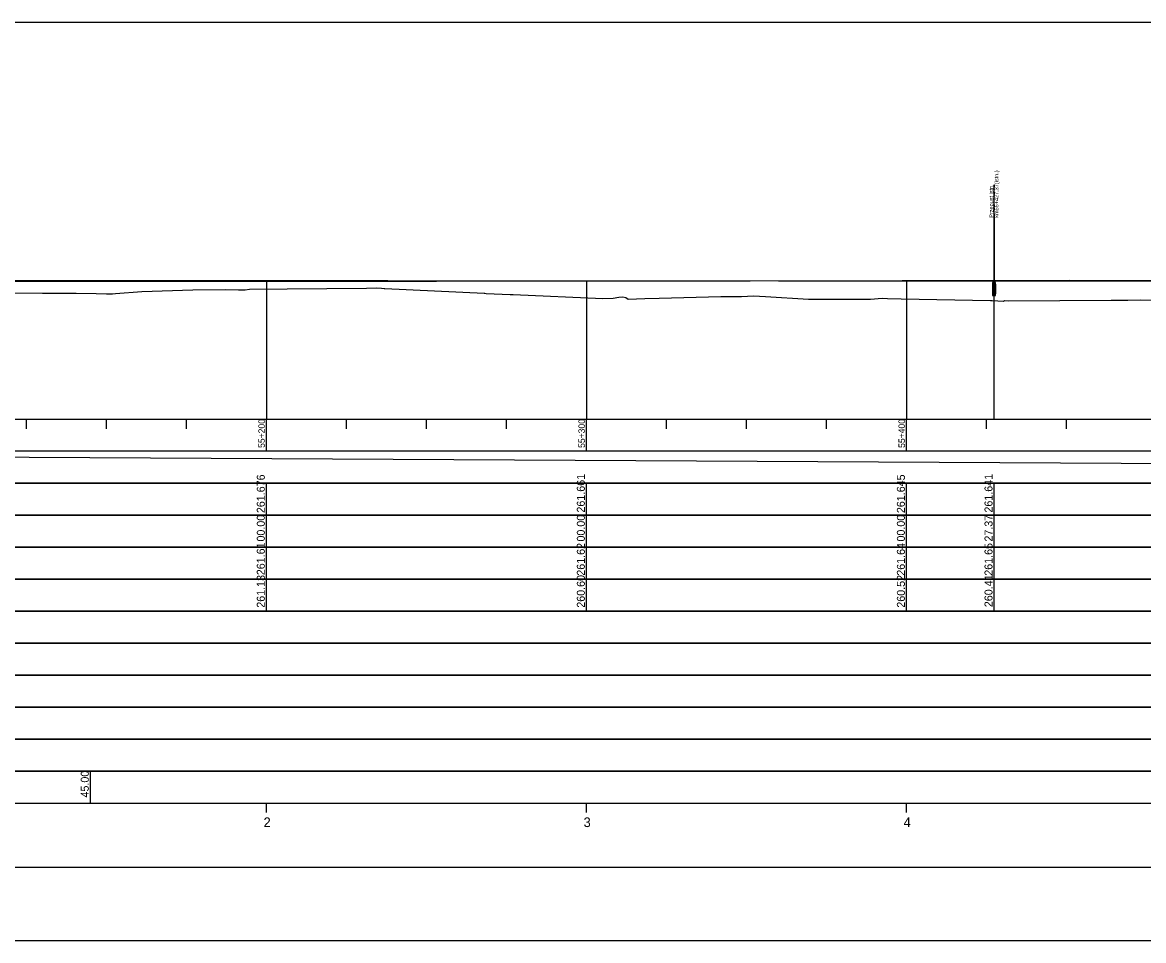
# Model space of a CAD drawing. Extents: x 6445630 to 6518227, y 5499240 to 5511716.
# Drawn here: x 6454355 to 6454705.3, y 5508966.7 to 5509253.7 of the extents above; entities that cross this region are included whole.
import ezdxf

# ---------------------------------------------------------------- set-up
doc = ezdxf.new("R2010")
doc.units = 0
for name, color, linetype in [('Default', 7, 'Continuous'), ('TOR_PROF-obiekty+opisy', 7, 'Continuous'), ('TOR_PROF-tabelka-geometria T1', 7, 'Continuous'), ('TOR_PROF-tabelka-kilometracja', 7, 'Continuous'), ('TOR_PROF-tabelka-odleglosci T1', 7, 'Continuous'), ('TOR_PROF-tabelka-pochylenia proj T1', 7, 'Continuous'), ('TOR_PROF-tabelka-rodzaj rowu T1', 7, 'Continuous'), ('TOR_PROF-tabelka-rowyT1', 7, 'Continuous'), ('TOR_PROF-tabelka-rurociagi T1', 7, 'Continuous'), ('TOR_PROF-tabelka-rzedne istn T1', 7, 'Continuous'), ('TOR_PROF-tabelka-rzedne proj T1', 7, 'Continuous'), ('TOR_PROF-tabelka-teren istniejacy T1', 7, 'Continuous'), ('TOR_PROF-tabelka-warstwa ochronna T1', 7, 'Continuous'), ('TOR_PROF-tor istniejacy T1', 7, 'Continuous'), ('TOR_PROF-tor projektowany', 7, 'Continuous'), ('TOR_PROF-uklad odniesienia', 7, 'Continuous'), ('TOR_PROF-warstwa ochronna', 7, 'Continuous'), ('TOR_RAMKI-dodatkowe3', 7, 'Continuous'), ('TOR_RAMKI-MASKA WYCIECIA', 7, 'Continuous')]:
    doc.layers.add(name, color=color, linetype=linetype)

msp = doc.modelspace()

# ---------------------------------------------------------------- linework, layer by layer
at = {"layer": 'TOR_PROF-obiekty+opisy'}
for p, q in [((6454658.59, 5509129.74), (6454658.59, 5509202.94)), ((6454658.59, 5509193.94), (6454658.59, 5509172.94)), ((6454658.59, 5509193.94), (6454658.59, 5509172.94))]:
    msp.add_line(p, q, dxfattribs=at)
for points in [[(6454659.05, 5509172.45), (6454658.13, 5509172.45), (6454658.13, 5509168.37), (6454659.05, 5509168.37)], [(6454658.97, 5509171.91), (6454658.22, 5509171.91), (6454658.22, 5509168.91), (6454658.97, 5509168.91)]]:
    msp.add_lwpolyline(points, close=True, dxfattribs=at)
for points in [[(6454659.05, 5509168.37), (6454659.05, 5509172.45), (6454658.13, 5509172.45), (6454658.13, 5509168.37), (6454659.05, 5509168.37)], [(6454658.97, 5509168.91), (6454658.22, 5509168.91), (6454658.22, 5509171.91), (6454658.97, 5509171.91), (6454658.97, 5509168.91)]]:
    msp.add_lwpolyline(points, dxfattribs=at)
at = {"layer": 'TOR_PROF-tabelka-geometria T1'}
for points in [[(6452331.21, 5508989.74), (6462728.4, 5508989.74)], [(6452331.21, 5508989.74), (6462731.21, 5508989.74)]]:
    msp.add_lwpolyline(points, dxfattribs=at)
at = {"layer": 'TOR_PROF-tabelka-kilometracja'}
for points in [[(6454431.21, 5509006.74), (6454431.21, 5509009.74)], [(6454531.21, 5509006.74), (6454531.21, 5509009.74)], [(6454631.21, 5509006.74), (6454631.21, 5509009.74)]]:
    msp.add_lwpolyline(points, dxfattribs=at)
at = {"layer": 'TOR_PROF-tabelka-odleglosci T1'}
msp.add_lwpolyline([(6452331.21, 5509089.74), (6462731.21, 5509089.74), (6462731.21, 5509099.74), (6452331.21, 5509099.74)], close=True, dxfattribs=at)
for points in [[(6454431.21, 5509089.74), (6454431.21, 5509099.74)], [(6454531.21, 5509089.74), (6454531.21, 5509099.74)], [(6454631.21, 5509089.74), (6454631.21, 5509099.74)], [(6454658.59, 5509089.74), (6454658.59, 5509099.74)]]:
    msp.add_lwpolyline(points, dxfattribs=at)
at = {"layer": 'TOR_PROF-tabelka-pochylenia proj T1'}
msp.add_lwpolyline([(6452331.21, 5509109.74), (6462731.21, 5509109.74), (6462731.21, 5509119.74), (6452331.21, 5509119.74)], close=True, dxfattribs=at)
msp.add_lwpolyline([(6454281.21, 5509118.24), (6455551.21, 5509111.24)], dxfattribs=at)
at = {"layer": 'TOR_PROF-tabelka-rodzaj rowu T1'}
for points in [[(6452331.21, 5509049.74), (6462731.21, 5509049.74), (6462731.21, 5509059.74), (6452331.21, 5509059.74)], [(6452331.21, 5509029.74), (6462731.21, 5509029.74), (6462731.21, 5509039.74), (6452331.21, 5509039.74)]]:
    msp.add_lwpolyline(points, close=True, dxfattribs=at)
at = {"layer": 'TOR_PROF-tabelka-rowyT1'}
msp.add_lwpolyline([(6452331.21, 5509059.74), (6462731.21, 5509059.74), (6462731.21, 5509069.74), (6452331.21, 5509069.74)], close=True, dxfattribs=at)
at = {"layer": 'TOR_PROF-tabelka-rurociagi T1'}
msp.add_lwpolyline([(6452331.21, 5509039.74), (6462731.21, 5509039.74), (6462731.21, 5509049.74), (6452331.21, 5509049.74)], close=True, dxfattribs=at)
at = {"layer": 'TOR_PROF-tabelka-rzedne istn T1'}
msp.add_lwpolyline([(6452331.21, 5509079.74), (6462731.21, 5509079.74), (6462731.21, 5509089.74), (6452331.21, 5509089.74)], close=True, dxfattribs=at)
for points in [[(6454431.21, 5509079.74), (6454431.21, 5509089.74)], [(6454531.21, 5509079.74), (6454531.21, 5509089.74)], [(6454631.21, 5509079.74), (6454631.21, 5509089.74)], [(6454658.59, 5509079.74), (6454658.59, 5509089.74)], [(6454431.21, 5509069.74), (6454431.21, 5509079.74)], [(6454431.21, 5509069.74), (6454431.21, 5509079.74)], [(6454431.21, 5509069.74), (6454431.21, 5509079.74)], [(6454431.21, 5509069.74), (6454431.21, 5509079.74)], [(6454431.21, 5509069.74), (6454431.21, 5509079.74)], [(6454531.21, 5509069.74), (6454531.21, 5509079.74)], [(6454531.21, 5509069.74), (6454531.21, 5509079.74)], [(6454531.21, 5509069.74), (6454531.21, 5509079.74)], [(6454531.21, 5509069.74), (6454531.21, 5509079.74)], [(6454531.21, 5509069.74), (6454531.21, 5509079.74)], [(6454631.21, 5509069.74), (6454631.21, 5509079.74)], [(6454631.21, 5509069.74), (6454631.21, 5509079.74)], [(6454631.21, 5509069.74), (6454631.21, 5509079.74)], [(6454631.21, 5509069.74), (6454631.21, 5509079.74)], [(6454631.21, 5509069.74), (6454631.21, 5509079.74)], [(6454658.59, 5509069.74), (6454658.59, 5509079.74)]]:
    msp.add_lwpolyline(points, dxfattribs=at)
at = {"layer": 'TOR_PROF-tabelka-rzedne proj T1'}
msp.add_lwpolyline([(6452331.21, 5509099.74), (6462731.21, 5509099.74), (6462731.21, 5509109.74), (6452331.21, 5509109.74)], close=True, dxfattribs=at)
for points in [[(6454431.21, 5509099.74), (6454431.21, 5509109.74)], [(6454531.21, 5509099.74), (6454531.21, 5509109.74)], [(6454631.21, 5509099.74), (6454631.21, 5509109.74)], [(6454658.59, 5509099.74), (6454658.59, 5509109.74)]]:
    msp.add_lwpolyline(points, dxfattribs=at)
at = {"layer": 'TOR_PROF-tabelka-teren istniejacy T1'}
msp.add_lwpolyline([(6452331.21, 5509069.74), (6462731.21, 5509069.74), (6462731.21, 5509079.74), (6452331.21, 5509079.74)], close=True, dxfattribs=at)
msp.add_lwpolyline([(6452331.21, 5509069.74), (6462731.21, 5509069.74), (6462731.21, 5509079.74), (6452331.21, 5509079.74)], close=True, dxfattribs=at)
msp.add_lwpolyline([(6452331.21, 5509069.74), (6462731.21, 5509069.74), (6462731.21, 5509079.74), (6452331.21, 5509079.74)], close=True, dxfattribs=at)
msp.add_lwpolyline([(6452331.21, 5509069.74), (6462731.21, 5509069.74), (6462731.21, 5509079.74), (6452331.21, 5509079.74)], close=True, dxfattribs=at)
msp.add_lwpolyline([(6452331.21, 5509069.74), (6462731.21, 5509069.74), (6462731.21, 5509079.74), (6452331.21, 5509079.74)], close=True, dxfattribs=at)
at = {"layer": 'TOR_PROF-tabelka-warstwa ochronna T1'}
msp.add_lwpolyline([(6452331.21, 5509019.74), (6462731.21, 5509019.74), (6462731.21, 5509029.74), (6452331.21, 5509029.74)], close=True, dxfattribs=at)
at = {"layer": 'TOR_PROF-tor istniejacy T1'}
msp.add_lwpolyline([(6455080.92, 5509173.34), (6455031.47, 5509173.29), (6454982.25, 5509173.29), (6454932.13, 5509173.19), (6454881.27, 5509173.14), (6454830.82, 5509173.04), (6454782.24, 5509173.04), (6454734.36, 5509172.99), (6454682.23, 5509173.04), (6454629.84, 5509172.94), (6454582.4, 5509172.89), (6454537.18, 5509172.84), (6454484.35, 5509172.79), (6454432.02, 5509172.79), (6454381.42, 5509172.74), (6454331.32, 5509172.69)], dxfattribs=at)
at = {"layer": 'TOR_PROF-tor projektowany'}
msp.add_line((6454281.21, 5509173.24), (6455551.21, 5509172.24), dxfattribs=at)
msp.add_line((6454281.21, 5509173.24), (6455551.21, 5509172.24), dxfattribs=at)
for points in [[(6454431.21, 5509173.12), (6454431.21, 5509134.74), (6454431.21, 5509129.74), (6454431.21, 5509129.74)], [(6454431.21, 5509173.12), (6454431.21, 5509134.74), (6454431.21, 5509129.74), (6454431.21, 5509129.74)], [(6454531.21, 5509173.04), (6454531.21, 5509134.74), (6454531.21, 5509129.74), (6454531.21, 5509129.74)], [(6454531.21, 5509173.04), (6454531.21, 5509134.74), (6454531.21, 5509129.74), (6454531.21, 5509129.74)], [(6454631.21, 5509172.96), (6454631.21, 5509134.74), (6454631.21, 5509129.74), (6454631.21, 5509129.74)], [(6454631.21, 5509172.96), (6454631.21, 5509134.74), (6454631.21, 5509129.74), (6454631.21, 5509129.74)]]:
    msp.add_lwpolyline(points, dxfattribs=at)
at = {"layer": 'TOR_PROF-uklad odniesienia'}
for p, q in [((6452331.21, 5509129.74), (6462731.21, 5509129.74)), ((6454356.21, 5509126.74), (6454356.21, 5509129.74)), ((6454381.21, 5509126.74), (6454381.21, 5509129.74)), ((6454406.21, 5509126.74), (6454406.21, 5509129.74)), ((6454431.21, 5509119.74), (6454431.21, 5509129.74)), ((6454456.21, 5509126.74), (6454456.21, 5509129.74)), ((6454481.21, 5509126.74), (6454481.21, 5509129.74)), ((6454506.21, 5509126.74), (6454506.21, 5509129.74)), ((6454531.21, 5509119.74), (6454531.21, 5509129.74)), ((6454556.21, 5509126.74), (6454556.21, 5509129.74)), ((6454581.21, 5509126.74), (6454581.21, 5509129.74)), ((6454606.21, 5509126.74), (6454606.21, 5509129.74)), ((6454631.21, 5509119.74), (6454631.21, 5509129.74)), ((6454656.21, 5509126.74), (6454656.21, 5509129.74)), ((6454681.21, 5509126.74), (6454681.21, 5509129.74))]:
    msp.add_line(p, q, dxfattribs=at)
at = {"layer": 'TOR_PROF-warstwa ochronna'}
msp.add_lwpolyline([(6452331.21, 5509009.74), (6462731.21, 5509009.74), (6462731.21, 5509019.74), (6452331.21, 5509019.74)], close=True, dxfattribs=at)
msp.add_lwpolyline([(6454376.21, 5509009.74), (6454376.21, 5509019.74)], dxfattribs=at)
at = {"layer": 'TOR_RAMKI-dodatkowe3'}
for p, q in [((6454352.44, 5509169.17), (6454361.21, 5509169.11)), ((6454361.21, 5509169.11), (6454371.83, 5509169.08)), ((6454371.83, 5509169.08), (6454378.02, 5509169.03)), ((6454378.02, 5509169.03), (6454381.22, 5509168.92)), ((6454381.22, 5509168.92), (6454383.18, 5509168.91)), ((6454383.18, 5509168.91), (6454384.03, 5509168.98)), ((6454384.03, 5509168.98), (6454392.34, 5509169.68)), ((6454392.34, 5509169.68), (6454408.25, 5509170.19)), ((6454408.25, 5509170.19), (6454418.51, 5509170.29)), ((6454418.51, 5509170.29), (6454422.49, 5509170.11)), ((6454422.49, 5509170.11), (6454424.61, 5509170.11)), ((6454424.61, 5509170.11), (6454425.92, 5509170.33)), ((6454425.92, 5509170.33), (6454437.7, 5509170.47)), ((6454437.7, 5509170.47), (6454462.45, 5509170.66)), ((6454462.45, 5509170.66), (6454465.66, 5509170.75)), ((6454465.66, 5509170.75), (6454467.17, 5509170.73)), ((6454467.17, 5509170.73), (6454468.06, 5509170.58)), ((6454468.06, 5509170.58), (6454468.27, 5509170.57)), ((6454468.27, 5509170.57), (6454499.21, 5509169.11)), ((6454499.21, 5509169.11), (6454499.34, 5509169.1)), ((6454499.34, 5509169.1), (6454499.42, 5509169.1)), ((6454499.42, 5509169.1), (6454499.83, 5509169.04)), ((6454499.83, 5509169.04), (6454507.4, 5509168.75)), ((6454507.4, 5509168.75), (6454507.67, 5509168.73)), ((6454507.67, 5509168.73), (6454508.27, 5509168.7)), ((6454508.27, 5509168.7), (6454536.31, 5509167.5)), ((6454536.31, 5509167.5), (6454539.59, 5509167.52)), ((6454539.59, 5509167.52), (6454541.37, 5509167.91)), ((6454541.37, 5509167.91), (6454542.63, 5509167.93)), ((6454542.63, 5509167.93), (6454543.53, 5509167.74)), ((6454543.53, 5509167.74), (6454544.22, 5509167.28)), ((6454544.22, 5509167.28), (6454549.46, 5509167.47)), ((6454549.46, 5509167.47), (6454553.91, 5509167.59)), ((6454553.91, 5509167.59), (6454573.21, 5509168.04)), ((6454573.21, 5509168.04), (6454579.64, 5509168.05)), ((6454579.64, 5509168.05), (6454583.41, 5509168.27)), ((6454583.41, 5509168.27), (6454587.15, 5509168.05)), ((6454587.15, 5509168.05), (6454600.55, 5509167.26)), ((6454600.55, 5509167.26), (6454620.01, 5509167.2)), ((6454620.01, 5509167.2), (6454623.56, 5509167.53)), ((6454623.56, 5509167.53), (6454625.25, 5509167.46)), ((6454625.25, 5509167.46), (6454629.54, 5509167.38)), ((6454629.54, 5509167.38), (6454657.47, 5509166.82)), ((6454657.47, 5509166.82), (6454658.02, 5509166.79)), ((6454658.02, 5509166.79), (6454661.54, 5509166.64)), ((6454661.54, 5509166.64), (6454661.86, 5509166.79)), ((6454661.86, 5509166.79), (6454663.03, 5509166.76)), ((6454663.03, 5509166.76), (6454695.2, 5509166.89)), ((6454695.2, 5509166.89), (6454700.33, 5509166.9)), ((6454700.33, 5509166.9), (6454704.35, 5509167.02)), ((6454704.35, 5509167.02), (6454707.86, 5509166.93))]:
    msp.add_line(p, q, dxfattribs=at)
at = {"layer": 'TOR_RAMKI-MASKA WYCIECIA'}
msp.add_lwpolyline([(6454268.59, 5508966.75), (6456248.59, 5508966.75), (6456248.59, 5509253.75), (6454268.59, 5509253.75)], close=True, dxfattribs=at)

# ---------------------------------------------------------------- texts
at = {"layer": 'Default'}
for p in [(6454381.41, 5509172.74), (6454432.02, 5509172.79), (6454484.35, 5509172.79), (6454537.18, 5509172.84), (6454582.4, 5509172.89), (6454629.84, 5509172.94), (6454682.23, 5509173.04)]:
    msp.add_text('+', height=0.001, dxfattribs=at).set_placement(p)
at = {"layer": 'TOR_PROF-obiekty+opisy'}
for s, p in [(' km55+427,37(istn.) ', (6454659.93, 5509192.2)), (' Przepust istn.', (6454658.31, 5509192.2))]:
    msp.add_text(s, height=1.25, rotation=90, dxfattribs=at).set_placement(p)
at = {"layer": 'TOR_PROF-tabelka-kilometracja'}
for s, p in [('2', (6454430.33, 5509002.24)), ('3', (6454530.32, 5509002.24)), ('4', (6454630.32, 5509002.24))]:
    msp.add_text(s, height=3, dxfattribs=at).set_placement(p)
at = {"layer": 'TOR_PROF-tabelka-odleglosci T1'}
for s, p in [('00.00', (6454430.71, 5509091.48)), ('00.00', (6454530.71, 5509091.48)), ('00.00', (6454630.71, 5509091.48)), ('27.37', (6454658.09, 5509091.48))]:
    msp.add_text(s, height=2.5, rotation=90, dxfattribs=at).set_placement(p)
at = {"layer": 'TOR_PROF-tabelka-rzedne istn T1'}
for s, p in [('261.61', (6454430.71, 5509080.97)), ('261.62', (6454530.71, 5509080.81)), ('261.64', (6454630.71, 5509080.8)), ('261.65', (6454658.09, 5509080.8)), ('261.13', (6454430.71, 5509070.8)), ('260.60', (6454530.71, 5509070.8)), ('260.52', (6454630.71, 5509070.81)), ('260.41', (6454658.09, 5509070.97))]:
    msp.add_text(s, height=2.5, rotation=90, dxfattribs=at).set_placement(p)
at = {"layer": 'TOR_PROF-tabelka-rzedne proj T1'}
for s, p in [('261.676', (6454430.71, 5509100.37)), ('261.661', (6454530.71, 5509100.54)), ('261.645', (6454630.71, 5509100.37)), ('261.641', (6454658.09, 5509100.54))]:
    msp.add_text(s, height=2.5, rotation=90, dxfattribs=at).set_placement(p)
at = {"layer": 'TOR_PROF-uklad odniesienia'}
for s, p in [('55+200', (6454430.71, 5509120.76)), ('55+300', (6454530.71, 5509120.76)), ('55+400', (6454630.71, 5509120.76))]:
    msp.add_text(s, height=2, rotation=90, dxfattribs=at).set_placement(p)
at = {"layer": 'TOR_PROF-warstwa ochronna'}
msp.add_text('45.00', height=2.5, rotation=90, dxfattribs=at).set_placement((6454375.71, 5509011.48))

doc.saveas('drawing.dxf')
